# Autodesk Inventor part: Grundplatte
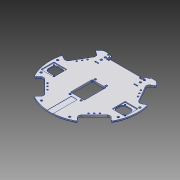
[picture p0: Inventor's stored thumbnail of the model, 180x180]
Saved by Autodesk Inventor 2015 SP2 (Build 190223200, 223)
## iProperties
Created: 2012-07
Part Number: Grundplatte
Material: Aluminium 6061
Document SubType Name: Modeling
Designer: rYan
Mass: 160.592 g
Surface Area: 391.117 cm^2
Volume: 59.259 cm^3
Density: 2.71 g/cm^3
Appearance: Aluminium - flach
Author: rYan
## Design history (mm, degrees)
sketch "Skizze1"
  geometry: L1 (0, 0)-(-76.21, 44); L2 (-128.085, 0)-(128.085, 0) reference; L3 (0, -123.2)-(0, 123.2) reference; L4 (0, 0)-(-62.225, -62.225); L5 (0, 0)-(76.21, 44); L6 (0, 0)-(76.21, 44); L7 (0, 0)-(62.225, -62.225); L8 (-61.321, 63.117)-(-48.189, 55.535); L9 (-48.189, 55.535)-(-72.189, 13.965); L10 (-72.189, 13.965)-(-85.321, 21.547); L11 (-76.837, -42.896)-(-66.114, -32.173); L12 (-66.114, -32.173)-(-32.173, -66.114); L13 (-32.173, -66.114)-(-42.896, -76.837); L14 (61.321, 63.117)-(48.189, 55.535); L15 (48.189, 55.535)-(72.189, 13.965); L16 (72.189, 13.965)-(85.321, 21.547); L17 (76.837, -42.896)-(66.114, -32.173); L18 (66.114, -32.173)-(32.173, -66.114); L19 (32.173, -66.114)-(42.896, -76.837); L20 (-51.99, 71)-(-36, 71); L21 (36, 71)-(51.99, 71); L22 (30, 62)-(-30, 62); L23 (36, 71)-(36, 59); L24 (-36, 71)-(-36, 59); L25 (-36, 59)-(-30, 59); L26 (-30, 59)-(-30, 62); L27 (36, 59)-(30, 59); L28 (30, 59)-(30, 62); A1 r 88 centre (0, 0) between (-85.321, 21.547) and (-76.837, -42.896); A2 r 88 centre (0, 0) between (76.837, -42.896) and (85.321, 21.547); A3 r 88 centre (0, 0) between (-42.896, -76.837) and (42.896, -76.837); A4 r 88 centre (0, 0) between (76.837, -42.896) and (85.321, 21.547); A5 r 88 centre (0, 0) between (61.321, 63.117) and (51.99, 71); A6 r 88 centre (0, 0) between (-51.99, 71) and (-61.321, 63.117); A7 r 88 centre (0, 0) between (-85.321, 21.547) and (-76.21, 44); 1 further point
  constraints: 52 end point, 16 point on circle, 11 symmetric about line, 7 centre point, 6 perpendicular, 3 coincident, 3 parallel, 2 horizontal, 1 concentric, 5 other
  dimensions: "d2" = 30 deg angle of L1 L2; "d4" = 45 deg angle of L4 L2; "d6" = 48 distance of L9.end L8.end; "d9" = 48 distance of L11.end L12.end (= d6); "d13" = 176 diameter of A7; "d130" = 71 distance between parallel lines of L2 L21; "d138" = 69.5 distance from line of point (0, 0) L9; "d139" = 62 distance between parallel lines of L2 L22; "d140" = 69.5 distance from line of L1.start L12 (derived); "d223" = 60 distance of L22.start L22.end; "d283" = 72 distance between parallel lines of L23 L24; "d284" = 3 distance between parallel lines of L22 L25
extrude "Extrusion1" new body sketch "Skizze1" distance "d14" = 4; taper "d15" = 0 deg
sketch "Skizze2"
  geometry: L1 (0, -119.8)-(0, 102.8) reference; L2 (-123.2, 0)-(123.2, 0) reference; L3 (11, 13)-(11, -37)
  constraints: 2 end point, 1 vertical
  dimensions: "d99" = 37 distance from line of L3.end L2; "d187" = 50 distance of L3.start L3.end; "d226" = 11 distance between parallel lines of L1 L3
hole "Kickerspule" sketch "Skizze2" at (11, -37), (11, 13) diameter "d21" = 4.2; stored, may be unused: countersink angle "d25" = 90 deg, drill point angle "d27" = 118 deg; dims "d22" = 6, "d23" = 7.5, "d24" = 2, "d26" = 8
sketch "Skizze3"
  geometry: L1 (48.189, 55.535)-(72.189, 13.965) reference; L2 (60.189, 34.75)-(57.071, 32.95); L3 (61.071, 26.022)-(53.071, 39.878); L4 (66.114, -32.173)-(32.173, -66.114) reference; L5 (49.144, -49.144)-(46.598, -46.598); L6 (52.255, -40.941)-(40.941, -52.255); L7 (0, 0)-(65.229, 37.66); A1 r 88 centre (0, 0) between (76.837, -42.896) and (85.321, 21.547) reference; 9 further points
  constraints: 10 end point, 6 coincident, 6 midpoint, 4 perpendicular, 1 collinear
  dimensions: "d29" = 16 distance of L3.start L3.end; "d30" = 3.6 distance of L5.end L5.start (derived); "d31" = 16 distance of L6.start L6.end (derived); "d76" = 0 distance from line of point (57.071, 32.95) L2; "d77" = 0 distance from line of point (46.598, -46.598) L5 (computed from d76); "d180" = 3.6 distance between parallel lines of L1 L3
hole "Lagerblöcke" sketch "Skizze3" diameter "d32" = 3.2; stored, may be unused: countersink angle "d36" = 90 deg, drill point angle "d38" = 118 deg; dims "d33" = 6, "d34" = 6, "d35" = 2, "d37" = 8
sketch "Skizze10"
  geometry: L1 (0, -119.8)-(0, 102.8) reference; L2 (-123.2, 0)-(123.2, 0) reference; L3 (39, 61)-(39, 53); 1 further point
  constraints: 2 end point, 1 vertical
  dimensions: "d237" = 39 distance between parallel lines of L1 L3; "d238" = 61 distance from line of L2 L3.start; "d239" = 8 distance of L3.start L3.end
hole "Dribbling" sketch "Skizze10" at (39, 53), (39, 61) diameter "d121" = 4.2; stored, may be unused: countersink angle "d125" = 90 deg, drill point angle "d127" = 118 deg; dims "d122" = 6, "d123" = 7.5, "d124" = 2, "d126" = 8
sketch "Skizze6"
  geometry: L1 (0, -119.8)-(0, 102.8) reference; L2 (-123.2, 0)-(123.2, 0) reference; 4 further points
  dimensions: "d65" = 77 distance from line of point (28, -77) L2; "d66" = 28 distance from line of L1 point (28, -77); "d67" = 82 distance from line of L1 point (82, 9); "d68" = 9 distance from line of L2 point (82, 9); "d240" = 29 distance from line of point (77, -29) L2; "d241" = 77 distance from line of L1 point (77, -29)
hole "Streben" sketch "Skizze6" at (82, 9), (28, -77), (77, -29) diameter "d69" = 4.2; stored, may be unused: countersink angle "d73" = 90 deg, drill point angle "d75" = 118 deg; dims "d70" = 6, "d71" = 7.5, "d72" = 2, "d74" = 8
sketch "Skizze22"
  geometry: L1 (0, 102.8)-(0, -119.8) reference; L2 (-123.2, 0)-(123.2, 0) reference; 5 further points
  dimensions: "d242" = 19 horizontal distance of point (-60, -20.4) point (-79, -1.4); "d265" = 60 distance from line of L1 point (-60, -20.4); "d266" = 19 horizontal distance of point (-60, -20.4) point (-79, -1.4); "d267" = 60 distance from line of L1 point (60, 1.4) (derived); "d268" = 19 horizontal distance of point (60, 1.4) point (79, -17.6); "d269" = 1.4 distance from line of L2 point (-79, -1.4); "d270" = 19 horizontal distance of point (79, -17.6) point (60, 1.4); "d271" = 1.4 distance from line of L2 point (60, 1.4)
hole "Maussensor" sketch "Skizze22" at (-79, -1.4), (-60, -20.4), (60, 1.4), (79, -17.6) diameter "d246" = 2.459; stored, may be unused: countersink angle "d250" = 90 deg, drill point angle "d252" = 118 deg; dims "d247" = 6, "d248" = 4, "d249" = 2, "d251" = 8
sketch "Skizze23"
  geometry: L1 (-56.93, -6.5)-(-56.93, -12.5); L2 (-71.93, 0.5)-(-63.93, 0.5); L3 (-63.93, -19.5)-(-71.93, -19.5); L4 (-78.93, -12.5)-(-78.93, -6.5); L5 (-67.93, 0.5)-(-67.93, -19.5); L6 (-78.93, -9.5)-(-56.93, -9.5); L7 (67.93, 0.5)-(67.93, -19.5); L8 (71.93, -19.5)-(63.93, -19.5); L9 (63.93, 0.5)-(71.93, 0.5); L10 (56.93, -9.5)-(78.93, -9.5); L11 (56.93, -12.5)-(56.93, -6.5); L12 (78.93, -6.5)-(78.93, -12.5); C1 r 1.23 at (-60, -20.4) reference; C2 r 1.23 at (60, 1.4) reference; A1 r 7 centre (-63.93, -6.5) between (-56.93, -6.5) and (-63.93, 0.5); A2 r 7 centre (-63.93, -12.5) between (-63.93, -19.5) and (-56.93, -12.5); A3 r 7 centre (-71.93, -6.5) between (-71.93, 0.5) and (-78.93, -6.5); A4 r 7 centre (-71.93, -12.5) between (-78.93, -12.5) and (-71.93, -19.5); A5 r 7 centre (63.93, -12.5) between (56.93, -12.5) and (63.93, -19.5); A6 r 7 centre (63.93, -6.5) between (63.93, 0.5) and (56.93, -6.5); A7 r 7 centre (71.93, -6.5) between (78.93, -6.5) and (71.93, 0.5); A8 r 7 centre (71.93, -12.5) between (71.93, -19.5) and (78.93, -12.5); 8 further points
  constraints: 24 end point, 16 point on circle, 16 tangent, 12 point on line, 8 centre point, 8 midpoint, 6 equal radius, 4 parallel, 2 horizontal, 2 perpendicular
  dimensions: "d253" = 22 distance of point (-78.93, 0.5) point (-56.93, 0.5); "d254" = 20 distance of point (-56.93, 0.5) point (-56.93, -19.5); "d255" = 7 radius of A1; "d257" = 10.9 distance from line of L6 C1.centre; "d272" = 7.93 distance from line of L5 C1.centre; "d274" = 22 distance of point (56.93, 0.5) point (78.93, 0.5); "d275" = 20 distance of point (78.93, 0.5) point (78.93, -19.5); "d276" = 7 radius of A7; "d277" = 7.93 distance from line of L7 C2.centre; "d278" = 10.9 distance from line of L10 C2.centre
extrude "Extrusion10" cut sketch "Skizze23" stored distance "d258" = 3; taper "d259" = 0 deg
sketch "Skizze27"
  geometry: L1 (-82.5, 2.1)-(-56.5, 2.1); L2 (-56.5, 2.1)-(-56.5, -23.9); L3 (-56.5, -23.9)-(-82.5, -23.9); L4 (-82.5, -23.9)-(-82.5, 2.1); L5 (56.5, 4.9)-(82.5, 4.9); L6 (82.5, 4.9)-(82.5, -21.1); L7 (82.5, -21.1)-(56.5, -21.1); L8 (56.5, -21.1)-(56.5, 4.9); C1 r 1.23 at (-79, -1.4) reference; C2 r 1.23 at (-60, -20.4) reference; C3 r 1.23 at (60, 1.4) reference; 1 further point
  constraints: 16 end point, 4 parallel, 2 horizontal, 2 perpendicular
  dimensions: "d296" = 26 distance of L1.start L1.end (derived); "d297" = 26 distance of L1.end L2.end; "d298" = 3.5 distance from line of L1 C1.centre; "d299" = 3.5 distance from line of L4 C1.centre; "d300" = 26 distance of L5.start L5.end (derived); "d301" = 26 distance of L5.end L6.end (derived); "d302" = 3.5 distance from line of L5 C3.centre; "d303" = 3.5 distance from line of L8 C3.centre
extrude "Extrusion13" cut sketch "Skizze27" distance "d304" = 2; taper "d305" = 0 deg
fillet "Rundung9" dims "d306" = 1
sketch "Skizze26"
  geometry: L1 (36, 71)-(36, 59) reference; L2 (51.99, 71)-(36, 71) reference; L3 (36, 71)-(42, 71); L4 (42, 71)-(42, 67); L5 (42, 67)-(36, 67); L6 (36, 67)-(36, 71); L7 (35, 45.05)-(43, 45.05); L8 (43, 45.05)-(43, 42.95); L9 (43, 42.95)-(35, 42.95); L10 (35, 42.95)-(35, 45.05); 1 further point
  constraints: 16 end point, 3 parallel, 2 horizontal, 2 perpendicular
  dimensions: "d285" = 6 distance of L4.end L5.end; "d286" = 4 distance of L3.end L4.end; "d287" = 8 distance of L8.end L9.end; "d288" = 2.1 distance of L7.end L8.end; "d289" = 21.95 distance between parallel lines of L7 L5; "d292" = 1 distance between parallel lines of L10 L1
extrude "Extrusion12" cut sketch "Skizze26" distance "d290" = 2; taper "d291" = 0 deg
fillet "Rundung7" dims "d293" = 1
mirror "Spiegeln1"
fillet "Rundung3" dims "d181" = 6
chamfer "Fase2" distance "d182" = 1.5; stored, may be unused: second distance "d183" = 2, angle "d184" = 45 deg
fillet "Rundung4" dims "d185" = 2
sketch "Skizze20"
  geometry: L1 (14, -33.7)-(-14, -33.7); L2 (-14, -33.7)-(-14, 9.7); L3 (-14, 9.7)-(14, 9.7); L4 (14, 9.7)-(14, -33.7); L5 (11, -37)-(-11, -37); L6 (-11, -37)-(-11, 13); L7 (-11, 13)-(11, 13); L8 (11, 13)-(11, -37); L9 (0, -37)-(0, 13); L10 (11, -12)-(-11, -12); C1 r 3.75 at (11, -37) reference; C2 r 3.75 at (-11, -37) reference; C3 r 3.75 at (-11, 13) reference; C4 r 3.75 at (11, 13) reference; C5 r 2.1 at (11, -37) reference; 1 further point
  constraints: 20 end point, 4 midpoint, 4 perpendicular, 2 horizontal, 2 parallel, 2 other
  dimensions: "d228" = 3.3 distance between parallel lines of L5 L1; "d280" = 28 distance of L2.end L3.end
extrude "Extrusion8" cut sketch "Skizze20" stored distance "d229" = 10; taper "d230" = 0 deg
sketch "Skizze21"
  geometry: L1 (-6, -39.7)-(6, -39.7); L2 (6, -39.7)-(6, -89.7); L3 (6, -89.7)-(-6, -89.7); L4 (-6, -89.7)-(-6, -39.7); L5 (0, 103.14)-(0, -121.84) reference; 5 further points; 1 other entity
  constraints: 8 end point, 2 parallel, 1 horizontal, 1 perpendicular, 2 other
  dimensions: "d232" = 50 distance of L3.end L1.start; "d233" = 12 distance of L1.start L1.end; "d234" = 6 dimension on L1
extrude "Extrusion9" cut sketch "Skizze21" distance "d235" = 0.5; taper "d236" = 0 deg
fillet "Rundung5" dims "d281" = 1
fillet "Rundung6" dims "d282" = 2
fillet "Rundung8" dims "d294" = 1
node "Volumenkörper1"
other parameters: "d0" = 175, "d10" = 175
